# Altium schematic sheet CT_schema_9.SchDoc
size 278 x 170 mm
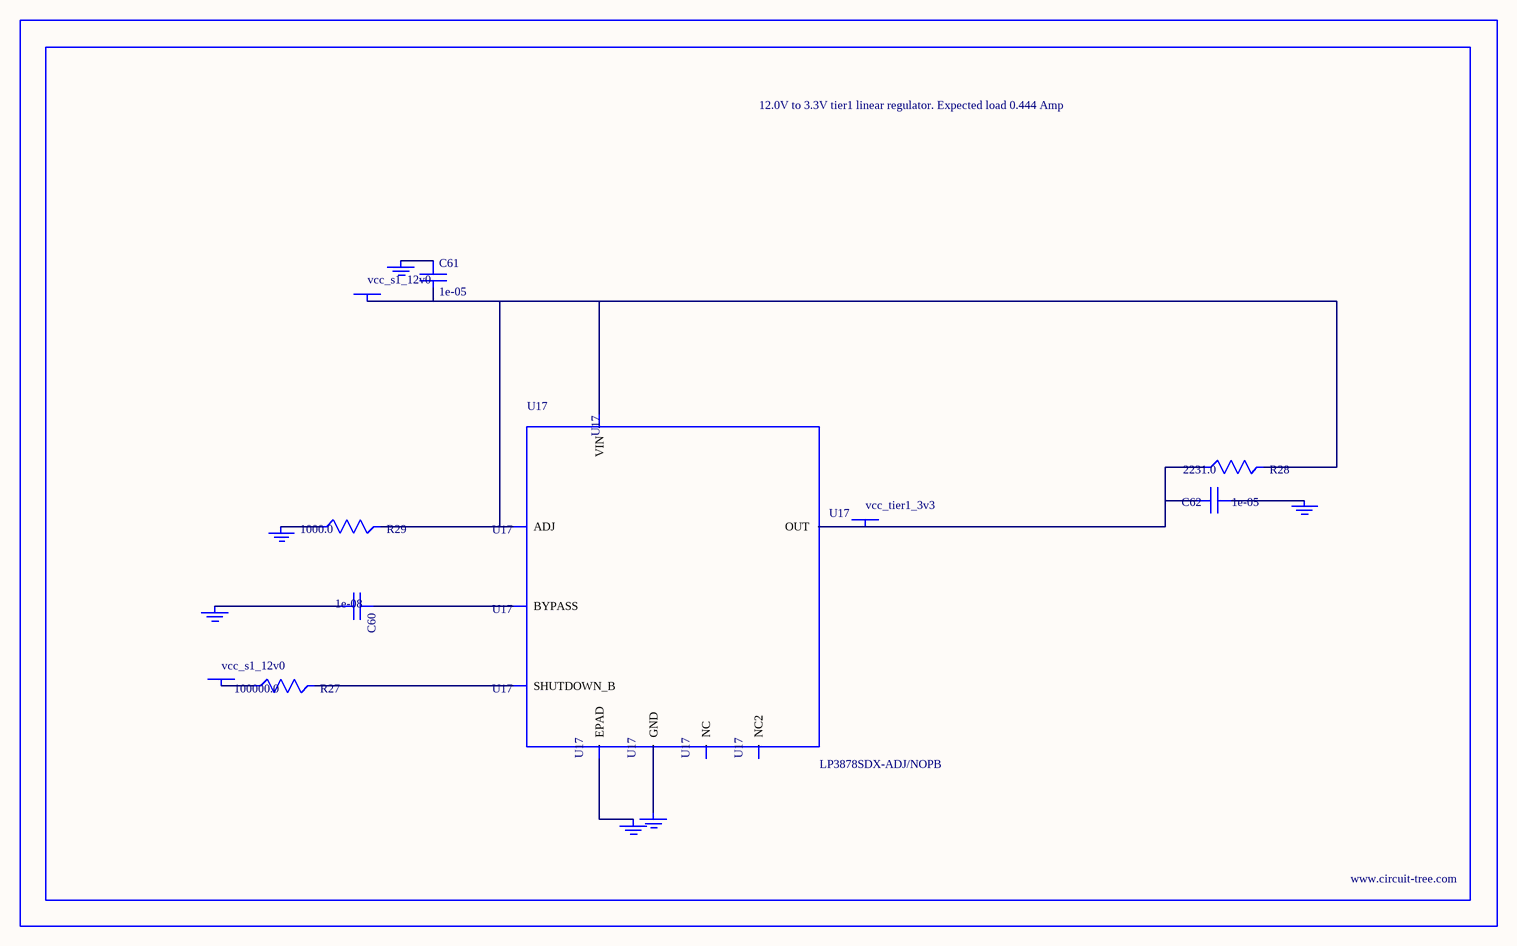
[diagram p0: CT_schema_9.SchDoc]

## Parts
BORDER8  (no value)
C60  1e-08  [C0402]
C61  1e-05  [C1210]
C62  1e-05  [C1210]
GND_INSTANCE_8_0  (no value)
GND_INSTANCE_8_1  (no value)
GND_INSTANCE_8_2  (no value)
GND_INSTANCE_8_3  (no value)
GND_INSTANCE_8_4  (no value)
GND_INSTANCE_8_5  (no value)
POWER_INSTANCE_8_0  vcc_s1_12v0
POWER_INSTANCE_8_1  vcc_s1_12v0
POWER_INSTANCE_8_2  vcc_tier1_3v3
R27  100000.0  [R0603]
R28  2231.0  [R0603]
R29  1000.0  [R0603]
U17  LP3878SDX-ADJ/NOPB  [WSON-8]

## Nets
NetC60_1: C60.1 U17.1(BYPASS)
NetC60_2: C60.2 GND_INSTANCE_8_0.0(GND)
NetC61_1: C61.1 GND_INSTANCE_8_1.0(GND)
NetC61_2: C61.2 POWER_INSTANCE_8_0.0(PWR) R28.2 R29.2 U17.4(VIN) U17.6(ADJ)
NetC62_1: C62.1 GND_INSTANCE_8_2.0(GND)
NetC62_2: C62.2 POWER_INSTANCE_8_2.0(PWR) R28.1 U17.5(OUT)
NetGND_INSTANCE_8_3_0: GND_INSTANCE_8_3.0(GND) R29.1
NetGND_INSTANCE_8_4_0: GND_INSTANCE_8_4.0(GND) U17.PAD(EPAD)
NetGND_INSTANCE_8_5_0: GND_INSTANCE_8_5.0(GND) U17.3(GND)
NetPOWER_INSTANCE_8_1_0: POWER_INSTANCE_8_1.0(PWR) R27.1
NetR27_2: R27.2 U17.8(SHUTDOWN_B)

Not connected (* = marked no-connect by the designer): U17 2(NC) 7(NC2)

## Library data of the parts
BORDER8 = BORDER_PAGE8
C60 = C0402C103K3RAC
C61 = C1210C106K5PACTU
C62 = GRM32DR61E106MA12L
GND_INSTANCE_8_0-GND_INSTANCE_8_5 = GND
POWER_INSTANCE_8_0-POWER_INSTANCE_8_2 = PWR
R27 = RC0603JR-07100KL
R28 = R28
R29 = RC0603JR-071KL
